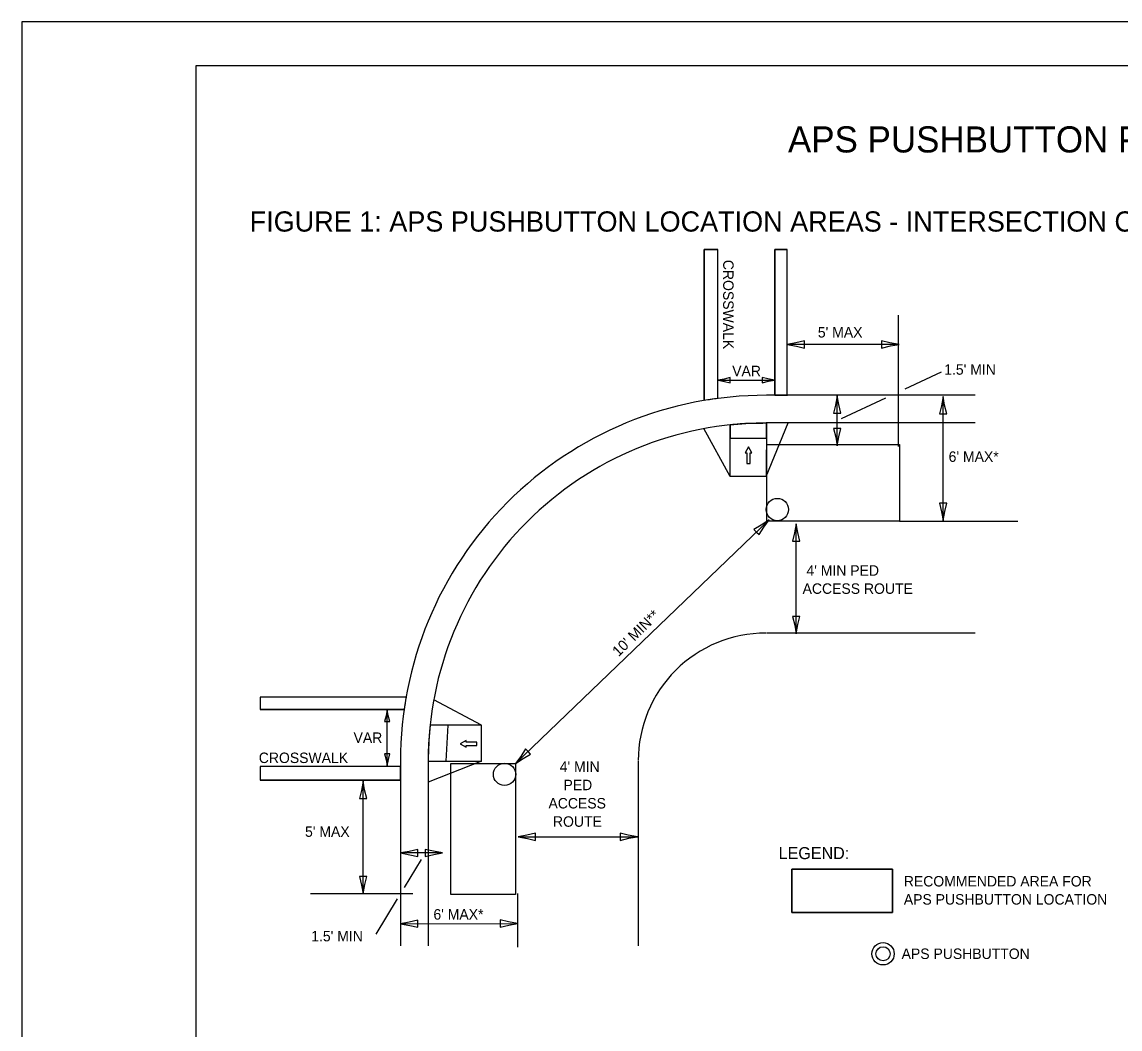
# Model space of a CAD drawing. Extents: x 1896459 to 1901611, y 1616229 to 1617416.
# Drawn here: x 1896459 to 1897089, y 1616838 to 1617416 of the extents above; entities that cross this region are included whole.
import ezdxf

# ---------------------------------------------------------------- set-up
doc = ezdxf.new("R2010")
doc.units = 0
for name, color, linetype in [('Drainage_EX_Hydraulic Study', 7, 'Continuous'), ('Level 24', 7, 'Continuous'), ('Level 32', 7, 'Continuous'), ('Level 8', 7, 'Continuous'), ('Sheets_General Details', 7, 'Continuous')]:
    doc.layers.add(name, color=color, linetype=linetype)

msp = doc.modelspace()

# ---------------------------------------------------------------- linework, layer by layer
at = {"layer": 'Drainage_EX_Hydraulic Study'}
for points in [[(1896877.08, 1617163.02), (1896877.08, 1617169.11), (1896878.04, 1617169.11), (1896876.12, 1617172.62), (1896874.2, 1617169.11), (1896875.16, 1617169.11), (1896875.16, 1617163.02)], [(1896720.21, 1617003.11), (1896714.12, 1617003.11), (1896714.12, 1617004.07), (1896710.61, 1617002.15), (1896714.12, 1617000.23), (1896714.12, 1617001.19), (1896720.21, 1617001.19)]]:
    msp.add_lwpolyline(points, close=True, dxfattribs=at)
at = {"layer": 'Level 24'}
for p, q in [((1896850.81, 1617285.83), (1896850.79, 1617199.17)), ((1896850.81, 1617285.83), (1896858.59, 1617285.83)), ((1896858.59, 1617285.83), (1896850.81, 1617285.83)), ((1896858.57, 1617200.34), (1896858.59, 1617285.83)), ((1896891.31, 1617285.82), (1896891.29, 1617202.14)), ((1896891.31, 1617285.82), (1896898.34, 1617285.82)), ((1896898.34, 1617285.82), (1896891.31, 1617285.82)), ((1896891.29, 1617202.14), (1896898.32, 1617202.14)), ((1896595.9, 1617028.83), (1896595.9, 1617021.81)), ((1896679.58, 1617028.83), (1896595.9, 1617028.83)), ((1896595.9, 1617028.83), (1896595.9, 1617021.81)), ((1896595.9, 1617021.81), (1896678.47, 1617021.81)), ((1896595.9, 1616989.08), (1896595.9, 1616981.31)), ((1896676.42, 1616989.08), (1896595.9, 1616989.08)), ((1896595.9, 1616989.08), (1896595.9, 1616981.31)), ((1896676.42, 1616981.31), (1896676.42, 1616989.08)), ((1896595.9, 1616981.31), (1896676.42, 1616981.31))]:
    msp.add_line(p, q, dxfattribs=at)
msp.add_lwpolyline([(1896898.32, 1617202.14), (1896898.33, 1617231.39), (1896898.34, 1617285.82)], dxfattribs=at)
for start, end in [(97.51461, 99.66413), (170.04112, 171.9864)]:
    msp.add_arc((1896885.97, 1616992.59), 209.55, start, end, dxfattribs=at)
at = {"layer": 'Level 32'}
for p, q in [((1896850.79, 1617199.17), (1896850.81, 1617285.83)), ((1896858.57, 1617200.34), (1896858.59, 1617285.83)), ((1896891.29, 1617202.08), (1896891.31, 1617285.82)), ((1896898.32, 1617201.78), (1896898.34, 1617285.82)), ((1896679.58, 1617028.83), (1896595.9, 1617028.83)), ((1896678.47, 1617021.81), (1896595.9, 1617021.81)), ((1896676.42, 1616989.08), (1896595.9, 1616989.08)), ((1896676.42, 1616981.31), (1896595.9, 1616981.31))]:
    msp.add_line(p, q, dxfattribs=at)
at = {"layer": 'Level 8'}
for p, q in [((1896962.36, 1617172.8), (1896962.36, 1617248.25)), ((1896962.61, 1617231.39), (1896898.33, 1617231.39)), ((1896966.05, 1617205.87), (1896986.95, 1617215.65)), ((1896858.68, 1617210.85), (1896891.08, 1617210.85)), ((1896927.14, 1617173.06), (1896927.14, 1617201.88)), ((1896929.48, 1617188.76), (1896954.95, 1617200.68)), ((1896987.9, 1617130.2), (1896987.9, 1617201.52)), ((1896742.38, 1616990.72), (1896887.98, 1617130.61)), ((1896903.6, 1617065.2), (1896903.6, 1617128.44)), ((1896962.77, 1617129.84), (1897030.84, 1617129.84)), ((1896668.75, 1616989.41), (1896668.75, 1617021.81)), ((1896654.88, 1616915.98), (1896654.88, 1616980.63)), ((1896743.97, 1616948.73), (1896812.46, 1616948.73)), ((1896700.59, 1616939.42), (1896676.36, 1616939.42)), ((1896678.7, 1616919.57), (1896688.52, 1616935.66)), ((1896683.38, 1616915.88), (1896624.73, 1616915.88)), ((1896662.43, 1616892.9), (1896674.71, 1616913.03)), ((1896743.63, 1616916.15), (1896743.63, 1616885.28)), ((1896676.42, 1616898.83), (1896743.63, 1616898.86))]:
    msp.add_line(p, q, dxfattribs=at)
for points in [[(1896908.33, 1617229.3), (1896908.33, 1617231.39), (1896908.33, 1617233.48), (1896903.33, 1617232.25), (1896898.33, 1617231.39), (1896903.66, 1617230.42)], [(1896952.61, 1617233.48), (1896952.6, 1617231.39), (1896952.6, 1617229.3), (1896957.61, 1617230.52), (1896962.61, 1617231.39), (1896957.27, 1617232.36)], [(1896865.68, 1617209.39), (1896865.68, 1617210.85), (1896865.68, 1617212.32), (1896862.18, 1617211.46), (1896858.68, 1617210.85), (1896862.41, 1617210.17)], [(1896884.08, 1617212.32), (1896884.08, 1617210.85), (1896884.08, 1617209.39), (1896887.58, 1617210.25), (1896891.08, 1617210.85), (1896887.35, 1617211.53)], [(1896925.04, 1617191.88), (1896927.14, 1617191.87), (1896929.23, 1617191.87), (1896928, 1617196.87), (1896927.14, 1617201.88), (1896926.17, 1617196.54)], [(1896985.81, 1617191.52), (1896987.9, 1617191.52), (1896989.99, 1617191.52), (1896988.76, 1617196.52), (1896987.9, 1617201.52), (1896986.93, 1617196.19)], [(1896929.23, 1617183.06), (1896927.14, 1617183.07), (1896925.04, 1617183.07), (1896926.27, 1617178.07), (1896927.14, 1617173.06), (1896928.11, 1617178.4)], [(1896989.99, 1617140.2), (1896987.9, 1617140.21), (1896985.81, 1617140.21), (1896987.03, 1617135.2), (1896987.9, 1617130.2), (1896988.87, 1617135.54)], [(1896879.32, 1617125.19), (1896880.77, 1617123.68), (1896882.22, 1617122.17), (1896884.97, 1617126.52), (1896887.98, 1617130.61), (1896883.46, 1617127.61)], [(1896901.51, 1617118.44), (1896903.6, 1617118.44), (1896905.7, 1617118.44), (1896904.47, 1617123.44), (1896903.6, 1617128.44), (1896902.63, 1617123.11)], [(1896905.7, 1617075.2), (1896903.6, 1617075.21), (1896901.51, 1617075.21), (1896902.74, 1617070.2), (1896903.6, 1617065.2), (1896904.57, 1617070.54)], [(1896667.29, 1617014.81), (1896668.75, 1617014.81), (1896670.22, 1617014.81), (1896669.36, 1617018.31), (1896668.75, 1617021.81), (1896668.08, 1617018.07)], [(1896751.04, 1616996.14), (1896749.6, 1616997.65), (1896748.15, 1616999.16), (1896745.39, 1616994.81), (1896742.38, 1616990.72), (1896746.9, 1616993.72)], [(1896670.22, 1616996.41), (1896668.75, 1616996.41), (1896667.29, 1616996.41), (1896668.15, 1616992.91), (1896668.75, 1616989.41), (1896669.43, 1616993.14)], [(1896652.79, 1616970.63), (1896654.88, 1616970.62), (1896656.98, 1616970.62), (1896655.75, 1616975.63), (1896654.88, 1616980.63), (1896653.91, 1616975.29)], [(1896753.97, 1616946.64), (1896753.98, 1616948.73), (1896753.98, 1616950.82), (1896748.97, 1616949.6), (1896743.97, 1616948.73), (1896749.31, 1616947.76)], [(1896802.46, 1616950.82), (1896802.45, 1616948.73), (1896802.45, 1616946.64), (1896807.46, 1616947.86), (1896812.46, 1616948.73), (1896807.12, 1616949.7)], [(1896686.36, 1616937.33), (1896686.36, 1616939.42), (1896686.36, 1616941.51), (1896681.36, 1616940.29), (1896676.36, 1616939.42), (1896681.69, 1616938.45)], [(1896690.59, 1616941.51), (1896690.59, 1616939.42), (1896690.59, 1616937.33), (1896695.59, 1616938.55), (1896700.59, 1616939.42), (1896695.26, 1616940.39)], [(1896656.98, 1616925.98), (1896654.88, 1616925.99), (1896652.79, 1616925.99), (1896654.02, 1616920.98), (1896654.88, 1616915.98), (1896655.85, 1616921.32)], [(1896686.42, 1616896.74), (1896686.43, 1616898.83), (1896686.43, 1616900.93), (1896681.42, 1616899.7), (1896676.42, 1616898.83), (1896681.76, 1616897.86)], [(1896733.63, 1616900.95), (1896733.63, 1616898.85), (1896733.63, 1616896.76), (1896738.63, 1616897.99), (1896743.63, 1616898.86), (1896738.3, 1616899.83)]]:
    msp.add_lwpolyline(points, close=True, dxfattribs=at)
at = {"layer": 'Sheets_General Details'}
for p, q in [((1896459.07, 1617416.47), (1896459.07, 1616316.47)), ((1898159.07, 1617416.47), (1896459.07, 1617416.47)), ((1897006.31, 1617202.14), (1896886.42, 1617202.14)), ((1896865.69, 1617155.61), (1896850.59, 1617183)), ((1896865.72, 1617185.2), (1896865.71, 1617177.34)), ((1896873.74, 1617185.87), (1896871.37, 1617185.71)), ((1896880.55, 1617186.18), (1896875.29, 1617185.96)), ((1896884.17, 1617186.25), (1896881.32, 1617186.2)), ((1896886.39, 1617155.59), (1896898.9, 1617186.26)), ((1897006.31, 1617186.26), (1896886.42, 1617186.26)), ((1896886.41, 1617177.57), (1896865.71, 1617177.34)), ((1896865.71, 1617177.34), (1896886.41, 1617177.57)), ((1897006.31, 1617065.66), (1896886.42, 1617065.66)), ((1896722.98, 1617012.88), (1896695.43, 1617027.26)), ((1896703.83, 1617012.88), (1896693.37, 1617012.88)), ((1896702.62, 1616992.18), (1896703.83, 1617012.88)), ((1896702.62, 1616992.18), (1896703.83, 1617012.88)), ((1896676.42, 1616992.14), (1896676.42, 1616886.13)), ((1896722.98, 1616992.18), (1896692.31, 1616980.06)), ((1896692.31, 1616992.14), (1896692.31, 1616886.13)), ((1896812.9, 1616992.14), (1896812.9, 1616886.13))]:
    msp.add_line(p, q, dxfattribs=at)
for points in [[(1896459.07, 1616316.47), (1898159.07, 1616316.47), (1898159.07, 1617416.47), (1896459.07, 1617416.47)], [(1896559.07, 1617391.47), (1898134.07, 1617391.47), (1898134.07, 1616341.47), (1896559.07, 1616341.47)], [(1896559.07, 1617391.46), (1898134.07, 1617391.46), (1898134.07, 1616391.47), (1896559.07, 1616391.47)], [(1896886.42, 1617186.26), (1896886.39, 1617155.59), (1896865.69, 1617155.61), (1896865.72, 1617185.21), (1896870.1, 1617185.62), (1896874.73, 1617185.94), (1896880.84, 1617186.19), (1896884.37, 1617186.25)], [(1896886.61, 1617173.82), (1896962.77, 1617173.82), (1896962.77, 1617129.84), (1896886.61, 1617129.84)], [(1896692.31, 1616992.18), (1896722.98, 1616992.18), (1896722.98, 1617012.88), (1896693.37, 1617012.88), (1896692.96, 1617008.49), (1896692.64, 1617003.87), (1896692.38, 1616997.76), (1896692.31, 1616994.23)], [(1896742.38, 1616915.58), (1896705.2, 1616915.58), (1896705.2, 1616990.72), (1896742.38, 1616990.72)], [(1896900.96, 1616930.04), (1896958.85, 1616930.04), (1896958.85, 1616905.3), (1896900.96, 1616905.3)]]:
    msp.add_lwpolyline(points, close=True, dxfattribs=at)
for points in [[(1896886.41, 1617177.57), (1896886.42, 1617186.26), (1896886.39, 1617186.26), (1896884.67, 1617186.25)], [(1896693.37, 1617012.88), (1896692.96, 1617008.49), (1896692.64, 1617003.87), (1896692.38, 1616997.76), (1896692.31, 1616994.23), (1896692.31, 1616992.18), (1896702.62, 1616992.18)], [(1896900.96, 1616905.3), (1896958.85, 1616905.3), (1896958.85, 1616930.04), (1896900.96, 1616930.04), (1896900.96, 1616905.3)]]:
    msp.add_lwpolyline(points, dxfattribs=at)
for centre, radius in [((1896892.72, 1617136.59), 6.41), ((1896736.13, 1616984.55), 6.41), ((1896953.41, 1616881.55), 6.41), ((1896953.41, 1616881.55), 4.05)]:
    msp.add_circle(centre, radius, dxfattribs=at)
for radius, start, end in [(209.55, 89.87691, 180.12309), (193.66, 89.87691, 180.12309), (193.66, 94.32422, 96.00194), (193.66, 93.1602, 93.62068), (193.66, 91.37605, 91.60356), (193.66, 90.38593, 90.53313), (73.07, 89.87691, 180.12309)]:
    msp.add_arc((1896885.97, 1616992.59), radius, start, end, dxfattribs=at)

# ---------------------------------------------------------------- texts
at = {"layer": 'Level 24'}
msp.add_text('APS PUSHBUTTON PLACEMENT DETAILS', height=15, dxfattribs=at).set_placement((1896898.82, 1617341.55))
at = {"layer": 'Level 8'}
for s, height, p in [('FIGURE 1: APS PUSHBUTTON LOCATION AREAS - INTERSECTION CORNER', 11.6, (1896589.8, 1617296.13)), ("5' MAX", 6, (1896915.99, 1617235.32)), ("1.5' MIN", 6, (1896988.54, 1617213.97)), ('VAR', 6, (1896866.82, 1617213.13)), ("6' MAX*", 6, (1896991.08, 1617163.94)), (" 4' MIN PED", 6, (1896907.22, 1617098.58)), ('ACCESS ROUTE', 6, (1896907.22, 1617088.18)), ('VAR', 6, (1896649.44, 1617002.61)), ('CROSSWALK', 6, (1896595.03, 1616991.06)), (" 4' MIN ", 6, (1896765.55, 1616985.97)), ('PED', 6, (1896769.95, 1616975.47)), ('ACCESS ', 6, (1896761.33, 1616964.97)), ("5' MAX", 6, (1896621.58, 1616948.68)), ('ROUTE', 6, (1896763.9, 1616954.47)), ('LEGEND:', 6.901, (1896893.48, 1616935.89)), ('RECOMMENDED AREA FOR ', 6, (1896965.34, 1616920.19)), ('APS PUSHBUTTON LOCATION', 6, (1896965.34, 1616909.79)), ("6' MAX*", 6, (1896695.29, 1616901.19)), ("1.5' MIN", 6, (1896625.14, 1616888.7)), ('APS PUSHBUTTON', 6, (1896964.07, 1616878.58))]:
    msp.add_text(s, height=height, dxfattribs=at).set_placement(p)
for s, rotation, p in [('CROSSWALK', 270, (1896861.62, 1617279.91)), ("10' MIN**", 44.36667, (1896801.51, 1617051.79))]:
    msp.add_text(s, height=6, rotation=rotation, dxfattribs=at).set_placement(p)

doc.saveas('drawing.dxf')
